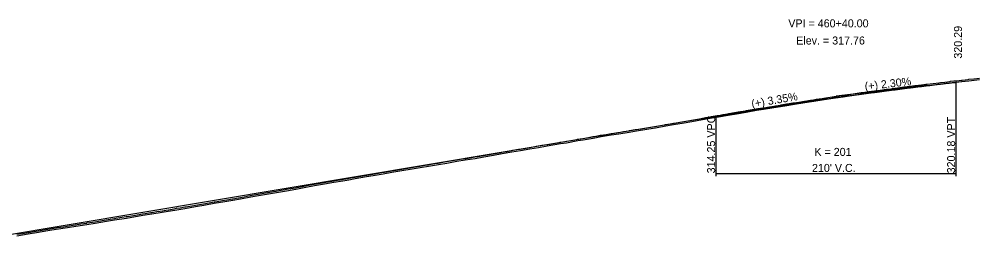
# Model space of a CAD drawing. Extents: x 1876258 to 1932803, y 754739 to 837911.
# Drawn here: x 1923688 to 1924528, y 831470 to 831660 of the extents above; entities that cross this region are included whole.
import ezdxf

# ---------------------------------------------------------------- set-up
doc = ezdxf.new("R2010")
doc.units = 0
for name, color, linetype in [('RD_DDB_GradeTX', 7, 'Continuous'), ('RD_DDB_Profile_EX', 7, 'Continuous'), ('RD_DDB_Profile_Lbl', 7, 'Continuous'), ('RD_DDB_Profile_PR', 7, 'Continuous'), ('RD_DDB_StripGrade', 7, 'Continuous'), ('RD_DDB_VCLbl', 7, 'Continuous'), ('RD_Sketch1', 7, 'Continuous')]:
    doc.layers.add(name, color=color, linetype=linetype)

msp = doc.modelspace()

# ---------------------------------------------------------------- linework, layer by layer
at = {"layer": 'RD_DDB_GradeTX'}
for p in [(1924482.56, 831602.26), (1924324.18, 831579.92)]:
    msp.add_line(p, (1924403.08, 831593.12), dxfattribs=at)
at = {"layer": 'RD_DDB_Profile_EX'}
for points in [[(1923930.15, 831511.79), (1923939.02, 831513.49), (1923946.55, 831514.84), (1923955.36, 831516.39), (1923963.53, 831517.74), (1923971.32, 831519.05), (1923976.49, 831519.97), (1923982.24, 831521.04), (1923992.14, 831522.78), (1923997.87, 831523.69), (1924006.74, 831525.29), (1924014.07, 831526.58), (1924022.95, 831528.05), (1924030.12, 831529.22), (1924038.86, 831530.65), (1924046.23, 831531.87), (1924054.91, 831533.31), (1924062.36, 831534.61), (1924071, 831536.08), (1924078.5, 831537.29), (1924087.16, 831538.68), (1924094.64, 831539.94), (1924103.24, 831541.46), (1924110.8, 831542.78), (1924119.29, 831544.35), (1924126.83, 831545.58), (1924134.95, 831546.94), (1924142.48, 831548.27), (1924150.08, 831549.55), (1924161.76, 831551.52), (1924167.18, 831552.38), (1924176.96, 831554.14), (1924181.57, 831554.89), (1924190.42, 831556.43), (1924197.39, 831557.67), (1924206.19, 831559.08), (1924212.95, 831560.17), (1924221.84, 831561.6), (1924228.4, 831562.7), (1924237.38, 831564.16), (1924244.92, 831565.38), (1924254.01, 831566.96), (1924260.78, 831568.14), (1924269.93, 831569.71), (1924276.61, 831570.86), (1924286.18, 831572.56), (1924292.75, 831573.71), (1924301.66, 831575.24), (1924308.37, 831576.35), (1924317.52, 831577.97), (1924324.22, 831579.1), (1924333.32, 831580.64), (1924339.33, 831581.57), (1924346.79, 831582.81), (1924354.35, 831584.01), (1924359.79, 831584.94), (1924366.53, 831586.01), (1924375.65, 831587.46), (1924383.37, 831588.64), (1924392.45, 831590.1), (1924400.29, 831591.14), (1924409.2, 831592.47), (1924416.19, 831593.49), (1924425.12, 831594.87), (1924434.18, 831596.07), (1924441.61, 831597.05), (1924450.84, 831598.24), (1924456.93, 831599.02), (1924462.86, 831599.89), (1924472.11, 831601.06), (1924481.45, 831602.17), (1924494.51, 831603.67), (1924502.46, 831604.66), (1924506.04, 831605.05), (1924512.67, 831605.71), (1924519.2, 831606.51), (1924528.41, 831607.55)], [(1923686.24, 831471.1), (1923696.1, 831472.71), (1923703.34, 831473.95), (1923713.28, 831475.56), (1923720.46, 831476.7), (1923730.31, 831478.27), (1923737.58, 831479.46), (1923747.42, 831480.97), (1923754.58, 831482.07), (1923764.48, 831483.69), (1923771.57, 831484.85), (1923771.6, 831484.85), (1923781.96, 831486.57), (1923788.4, 831487.65), (1923796.23, 831488.96), (1923804.32, 831490.27), (1923811.55, 831491.34), (1923816.72, 831492.21), (1923826.12, 831493.8), (1923833.19, 831495), (1923842.52, 831496.6), (1923849.71, 831497.83), (1923858.89, 831499.41), (1923866.2, 831500.68), (1923875.23, 831502.21), (1923881.88, 831503.35), (1923890.72, 831504.92), (1923897.44, 831506.14), (1923906.34, 831507.68), (1923913.34, 831508.87), (1923922.15, 831510.41), (1923930.15, 831511.79)]]:
    msp.add_lwpolyline(points, dxfattribs=at)
at = {"layer": 'RD_DDB_Profile_PR'}
for p, q in [((1924508.08, 831605.19), (1924513.08, 831605.77)), ((1923668.08, 831470.17), (1924298.08, 831575.55))]:
    msp.add_line(p, q, dxfattribs=at)
msp.add_spline([(1924298.08, 831575.55), (1924302.28, 831576.25), (1924306.48, 831576.95), (1924310.68, 831577.64), (1924314.88, 831578.33), (1924319.08, 831579.01), (1924323.28, 831579.69), (1924327.48, 831580.36), (1924331.68, 831581.03), (1924335.88, 831581.7), (1924340.08, 831582.36), (1924344.28, 831583.01), (1924348.48, 831583.67), (1924352.68, 831584.31), (1924356.88, 831584.96), (1924361.08, 831585.6), (1924365.28, 831586.23), (1924369.48, 831586.86), (1924373.68, 831587.49), (1924377.88, 831588.11), (1924382.08, 831588.72), (1924386.28, 831589.34), (1924390.48, 831589.95), (1924394.68, 831590.55), (1924398.88, 831591.15), (1924403.08, 831591.74), (1924407.28, 831592.33), (1924411.48, 831592.92), (1924415.68, 831593.5), (1924419.88, 831594.08), (1924424.08, 831594.65), (1924428.28, 831595.22), (1924432.48, 831595.79), (1924436.68, 831596.34), (1924440.88, 831596.9), (1924445.08, 831597.45), (1924449.28, 831598), (1924453.48, 831598.54), (1924457.68, 831599.08), (1924461.88, 831599.61), (1924466.08, 831600.14), (1924470.28, 831600.67), (1924474.48, 831601.19), (1924478.68, 831601.7), (1924482.88, 831602.21), (1924487.08, 831602.72), (1924491.28, 831603.22), (1924495.48, 831603.72), (1924499.68, 831604.22), (1924503.88, 831604.71), (1924508.08, 831605.19)], degree=3, dxfattribs=at)
at = {"layer": 'RD_DDB_VCLbl'}
for p, q in [((1924508.08, 831523.05), (1924508.08, 831605.19)), ((1924298.08, 831523.05), (1924298.08, 831575.55)), ((1924298.08, 831525.55), (1924508.08, 831525.55))]:
    msp.add_line(p, q, dxfattribs=at)
at = {"layer": 'RD_Sketch1'}
msp.add_lwpolyline([(1923686.04, 831472.34), (1923691.06, 831473.16), (1923695.9, 831473.94), (1923696.16, 831473.99), (1923701.26, 831474.87), (1923703.14, 831475.19), (1923706.38, 831475.71), (1923711.49, 831476.54), (1923713.09, 831476.79), (1923716.6, 831477.35), (1923720.26, 831477.94), (1923721.71, 831478.17), (1923726.81, 831478.98), (1923730.12, 831479.5), (1923731.91, 831479.8), (1923737.02, 831480.63), (1923737.39, 831480.69), (1923742.14, 831481.42), (1923747.23, 831482.2), (1923747.25, 831482.21), (1923752.35, 831482.99), (1923754.38, 831483.3), (1923757.45, 831483.8), (1923762.55, 831484.64), (1923764.28, 831484.92), (1923767.66, 831485.48), (1923771.44, 831486.09), (1923771.47, 831486.1), (1923772.76, 831486.31), (1923777.87, 831487.16), (1923781.76, 831487.8), (1923782.97, 831488.01), (1923788.08, 831488.87), (1923788.2, 831488.89), (1923793.19, 831489.72), (1923796.03, 831490.19), (1923798.3, 831490.56), (1923803.41, 831491.39), (1923804.13, 831491.5), (1923808.53, 831492.16), (1923811.35, 831492.57), (1923813.61, 831492.96), (1923816.52, 831493.45), (1923818.72, 831493.82), (1923823.83, 831494.68), (1923825.91, 831495.03), (1923828.93, 831495.55), (1923832.98, 831496.23), (1923834.04, 831496.41), (1923839.14, 831497.29), (1923842.31, 831497.84), (1923844.25, 831498.17), (1923849.36, 831499.04), (1923849.5, 831499.06), (1923854.46, 831499.92), (1923858.68, 831500.64), (1923859.57, 831500.79), (1923864.67, 831501.68), (1923865.99, 831501.91), (1923869.78, 831502.55), (1923874.89, 831503.42), (1923875.02, 831503.44), (1923880, 831504.29), (1923881.66, 831504.58), (1923885.09, 831505.19), (1923890.2, 831506.1), (1923890.51, 831506.15), (1923895.3, 831507.02), (1923897.22, 831507.37), (1923900.42, 831507.92), (1923905.53, 831508.81), (1923906.13, 831508.92), (1923910.64, 831509.68), (1923913.13, 831510.1), (1923915.74, 831510.56), (1923920.85, 831511.45), (1923921.94, 831511.64), (1923925.95, 831512.33), (1923929.93, 831513.02), (1923931.04, 831513.23), (1923936.14, 831514.21), (1923938.79, 831514.72), (1923941.27, 831515.16), (1923946.33, 831516.07), (1923946.38, 831516.08), (1923951.48, 831516.98), (1923955.15, 831517.62), (1923956.6, 831517.86), (1923961.71, 831518.71), (1923963.33, 831518.97), (1923966.81, 831519.56), (1923971.1, 831520.28), (1923971.91, 831520.42), (1923976.27, 831521.2), (1923977, 831521.34), (1923982.02, 831522.27), (1923982.12, 831522.29), (1923987.23, 831523.19), (1923991.94, 831524.02), (1923992.36, 831524.08), (1923997.46, 831524.89), (1923997.66, 831524.92), (1924002.54, 831525.81), (1924006.53, 831526.53), (1924007.66, 831526.72), (1924012.76, 831527.62), (1924013.86, 831527.81), (1924017.88, 831528.48), (1924022.75, 831529.28), (1924022.99, 831529.32), (1924028.1, 831530.16), (1924029.92, 831530.45), (1924033.2, 831530.99), (1924038.31, 831531.83), (1924038.66, 831531.89), (1924043.42, 831532.67), (1924046.03, 831533.1), (1924048.52, 831533.52), (1924053.63, 831534.36), (1924054.7, 831534.54), (1924058.72, 831535.24), (1924062.15, 831535.84), (1924063.83, 831536.13), (1924068.94, 831537), (1924070.79, 831537.31), (1924074.06, 831537.84), (1924078.31, 831538.52), (1924079.16, 831538.66), (1924084.27, 831539.48), (1924086.96, 831539.91), (1924089.37, 831540.32), (1924094.43, 831541.17), (1924094.47, 831541.18), (1924099.57, 831542.08), (1924103.02, 831542.69), (1924104.68, 831542.98), (1924109.79, 831543.87), (1924110.58, 831544.01), (1924114.88, 831544.8), (1924119.08, 831545.58), (1924120.01, 831545.73), (1924125.12, 831546.57), (1924126.62, 831546.82), (1924130.22, 831547.42), (1924134.73, 831548.17), (1924135.32, 831548.28), (1924140.43, 831549.18), (1924142.27, 831549.5), (1924145.54, 831550.06), (1924149.87, 831550.79), (1924150.65, 831550.92), (1924155.76, 831551.78), (1924160.86, 831552.63), (1924161.56, 831552.75), (1924165.98, 831553.45), (1924166.97, 831553.61), (1924171.06, 831554.35), (1924176.17, 831555.27), (1924176.75, 831555.37), (1924181.3, 831556.11), (1924181.37, 831556.12), (1924186.39, 831557), (1924190.21, 831557.66), (1924191.49, 831557.89), (1924196.6, 831558.8), (1924197.19, 831558.9), (1924201.72, 831559.63), (1924206, 831560.32), (1924206.83, 831560.45), (1924211.94, 831561.27), (1924212.75, 831561.4), (1924217.04, 831562.09), (1924221.64, 831562.83), (1924222.14, 831562.92), (1924227.25, 831563.77), (1924228.2, 831563.93), (1924232.36, 831564.61), (1924237.18, 831565.39), (1924237.47, 831565.44), (1924242.58, 831566.26), (1924244.72, 831566.61), (1924247.67, 831567.12), (1924252.77, 831568.02), (1924253.8, 831568.19), (1924257.88, 831568.91), (1924260.56, 831569.38), (1924262.99, 831569.79), (1924268.1, 831570.66), (1924269.72, 831570.94), (1924273.2, 831571.54), (1924276.39, 831572.09), (1924278.3, 831572.43), (1924283.41, 831573.34), (1924285.97, 831573.79), (1924288.52, 831574.24), (1924292.54, 831574.94), (1924293.63, 831575.13), (1924298.74, 831576.01), (1924301.46, 831576.48), (1924303.85, 831576.87), (1924308.16, 831577.58), (1924308.94, 831577.72), (1924314.05, 831578.63), (1924317.31, 831579.2), (1924319.17, 831579.52), (1924324.02, 831580.33), (1924324.27, 831580.37), (1924329.38, 831581.24), (1924333.12, 831581.87), (1924334.5, 831582.09), (1924339.14, 831582.8), (1924339.59, 831582.88), (1924344.7, 831583.73), (1924346.59, 831584.05), (1924349.82, 831584.56), (1924354.15, 831585.25), (1924354.91, 831585.38), (1924359.59, 831586.18), (1924360.03, 831586.25), (1924365.14, 831587.05), (1924366.33, 831587.24), (1924370.24, 831587.86), (1924375.35, 831588.68), (1924375.46, 831588.69), (1924380.46, 831589.46), (1924383.18, 831589.88), (1924385.56, 831590.26), (1924390.67, 831591.08), (1924392.27, 831591.33), (1924395.81, 831591.8), (1924400.12, 831592.37), (1924400.89, 831592.49), (1924406, 831593.26), (1924409.01, 831593.71), (1924411.11, 831594.01), (1924416, 831594.73), (1924416.21, 831594.76), (1924421.32, 831595.55), (1924424.94, 831596.11), (1924426.45, 831596.31), (1924431.56, 831596.98), (1924434.02, 831597.3), (1924436.66, 831597.66), (1924441.45, 831598.29), (1924441.77, 831598.33), (1924446.88, 831598.99), (1924450.69, 831599.48), (1924451.99, 831599.65), (1924456.76, 831600.26), (1924457.07, 831600.3), (1924462.18, 831601.05), (1924462.69, 831601.12), (1924467.31, 831601.71), (1924471.96, 831602.3), (1924472.42, 831602.36), (1924477.53, 831602.96), (1924481.31, 831603.41), (1924482.64, 831603.56), (1924487.75, 831604.15), (1924492.86, 831604.74), (1924494.37, 831604.92), (1924497.95, 831605.36), (1924502.32, 831605.9), (1924503.08, 831605.99), (1924505.91, 831606.3), (1924508.19, 831606.53), (1924512.53, 831606.96), (1924513.27, 831607.05), (1924518.38, 831607.67), (1924519.06, 831607.75), (1924523.5, 831608.25), (1924528.27, 831608.79)], dxfattribs=at)

# ---------------------------------------------------------------- texts
at = {"layer": 'RD_DDB_GradeTX'}
for s, rotation, p in [('(+) 2.30%', 6.5602, (1924428.36, 831598.04)), ('(+) 3.35%', 9.4961, (1924329.44, 831582.83))]:
    msp.add_text(s, height=7, rotation=rotation, dxfattribs=at).set_placement(p)
at = {"layer": 'RD_DDB_Profile_Lbl'}
for s, p in [('VPI = 460+40.00', (1924361.12, 831653.12)), ('Elev. = 317.76', (1924368.03, 831638.12))]:
    msp.add_text(s, height=7, dxfattribs=at).set_placement(p)
msp.add_text('320.29', height=7, rotation=90, dxfattribs=at).set_placement((1924513.08, 831625.77))
at = {"layer": 'RD_DDB_StripGrade'}
for s, p in [('314.25 VPC', (1924297.08, 831525.55)), ('320.18 VPT', (1924507.08, 831525.55))]:
    msp.add_text(s, height=7, rotation=90, dxfattribs=at).set_placement(p)
at = {"layer": 'RD_DDB_VCLbl'}
for s, p in [('K = 201', (1924383.95, 831540.8)), ("210' V.C.", (1924381.83, 831526.8))]:
    msp.add_text(s, height=7, dxfattribs=at).set_placement(p)

doc.saveas('drawing.dxf')
